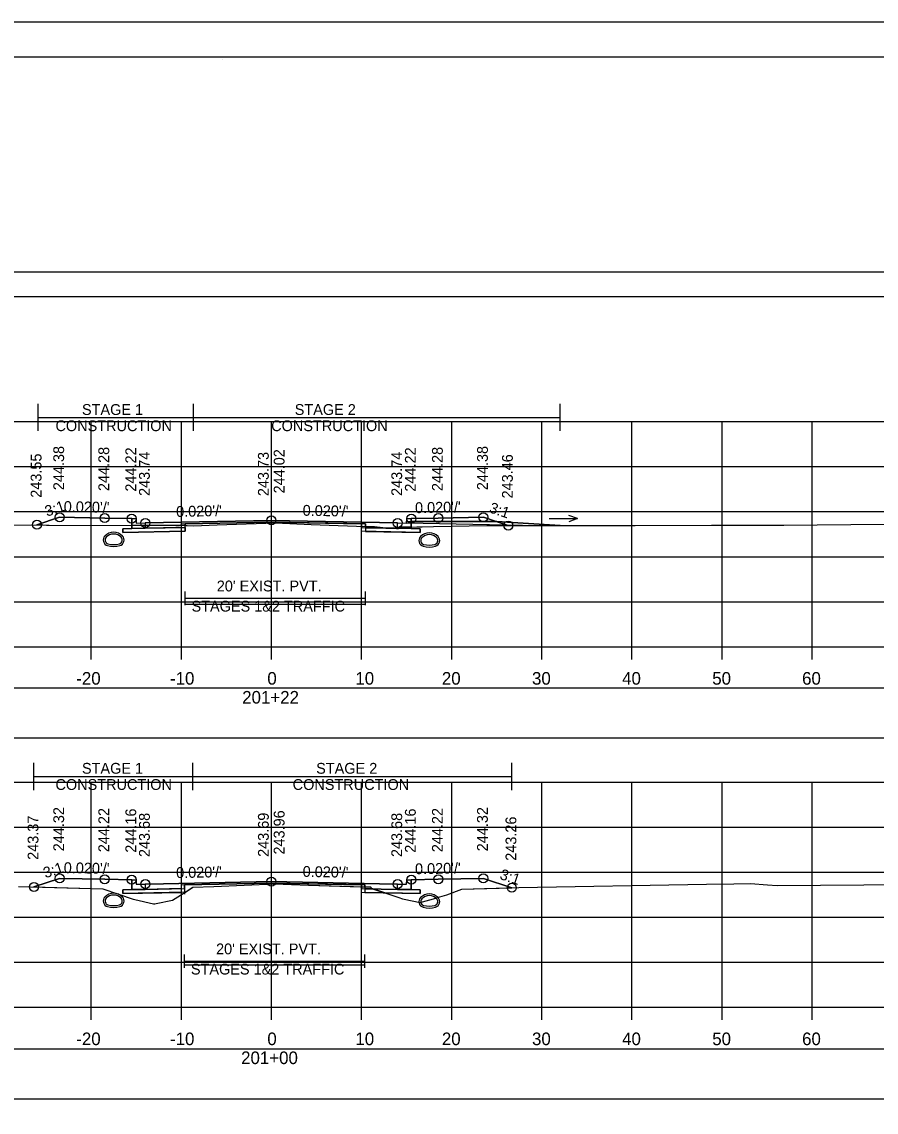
# Model space of a CAD drawing. Extents: x 1369627 to 1374022, y 380035 to 398173.
# Drawn here: x 1372070.8 to 1372165.6, y 380344.5 to 380465.5 of the extents above; entities that cross this region are included whole.
import ezdxf

# ---------------------------------------------------------------- set-up
doc = ezdxf.new("R2010")
doc.units = 0
for name, color, linetype in [('Default', 7, 'Continuous'), ('R_Alt Surface', 7, 'Continuous'), ('R_Axis', 7, 'Continuous'), ('R_Axis Annot', 7, 'Continuous'), ('R_Border', 7, 'Continuous'), ('R_Drive', 7, 'Continuous'), ('R_Exist Surface', 7, 'Continuous'), ('R_Fin Surface', 7, 'Continuous'), ('R_Grid', 7, 'Continuous'), ('R_MOT', 7, 'Continuous'), ('R_No Plot', 7, 'Continuous'), ('R_Water Annot', 7, 'Continuous'), ('R_Xsect Elev', 7, 'Continuous'), ('R_Xsect Slope', 7, 'Continuous'), ('T_Vehicle Path Lt Minor', 7, 'Continuous'), ('T_Vehicle Path Rt', 7, 'Continuous')]:
    doc.layers.add(name, color=color, linetype=linetype)

msp = doc.modelspace()

# ---------------------------------------------------------------- linework, layer by layer
at = {"layer": 'Default'}
for p, q in [((1372088.96, 380400.74), (1372088.96, 380402.24)), ((1372088.96, 380401.49), (1372108.96, 380401.49)), ((1372108.96, 380400.74), (1372108.96, 380402.24)), ((1372088.88, 380360.47), (1372088.88, 380361.97)), ((1372088.88, 380361.22), (1372108.88, 380361.22)), ((1372108.88, 380360.47), (1372108.88, 380361.97))]:
    msp.add_line(p, q, dxfattribs=at)
for points in [[(1371948.53, 380434.98), (1372248.53, 380434.98), (1372248.53, 380437.69), (1371948.53, 380437.69)], [(1372083.02, 380410.32), (1372083.52, 380410.32), (1372083.53, 380409.82), (1372084.53, 380409.84), (1372084.53, 380409.25), (1372083.03, 380409.22)], [(1372113.53, 380409.82), (1372113.54, 380410.32), (1372114.04, 380410.32), (1372114.03, 380409.22), (1372112.53, 380409.25), (1372112.53, 380409.84)], [(1371948.53, 380386.01), (1372248.53, 380386.01), (1372248.53, 380391.53), (1371948.53, 380391.53)], [(1372083.02, 380370.25), (1372083.52, 380370.25), (1372083.53, 380369.75), (1372084.53, 380369.77), (1372084.53, 380369.19), (1372083.03, 380369.16)], [(1372113.53, 380369.75), (1372113.54, 380370.25), (1372114.04, 380370.25), (1372114.03, 380369.16), (1372112.53, 380369.19), (1372112.53, 380369.77)], [(1371948.53, 380345.93), (1372248.53, 380345.93), (1372248.53, 380351.45), (1371948.53, 380351.45)]]:
    msp.add_lwpolyline(points, close=True, dxfattribs=at)
at = {"layer": 'R_Alt Surface'}
for points in [[(1372083.03, 380410.32), (1372083.03, 380409.22), (1372084.53, 380409.25), (1372088.96, 380409.34), (1372088.96, 380409.76), (1372098.53, 380409.95), (1372108.96, 380409.74), (1372108.96, 380409.32), (1372112.53, 380409.25), (1372114.03, 380409.22), (1372114.03, 380410.32)], [(1372083.03, 380370.25), (1372083.03, 380369.16), (1372084.53, 380369.19), (1372088.88, 380369.27), (1372088.88, 380369.69), (1372098.53, 380369.88), (1372108.88, 380369.68), (1372108.88, 380369.26), (1372112.53, 380369.19), (1372114.03, 380369.16), (1372114.03, 380370.25)]]:
    msp.add_lwpolyline(points, dxfattribs=at)
for points in [[(1372082.03, 380409.2), (1372083.03, 380409.22), (1372084.53, 380409.25), (1372088.96, 380409.34), (1372088.96, 380408.92), (1372082.03, 380408.79)], [(1372115.03, 380409.2), (1372114.03, 380409.22), (1372112.53, 380409.25), (1372108.96, 380409.32), (1372108.96, 380408.91), (1372115.03, 380408.79)], [(1372082.03, 380369.14), (1372083.03, 380369.16), (1372084.53, 380369.19), (1372088.88, 380369.27), (1372088.88, 380368.86), (1372082.03, 380368.72)], [(1372115.03, 380369.14), (1372114.03, 380369.16), (1372112.53, 380369.19), (1372108.88, 380369.26), (1372108.88, 380368.84), (1372115.03, 380368.72)]]:
    msp.add_lwpolyline(points, close=True, dxfattribs=at)
at = {"layer": 'R_Axis'}
for p, q in [((1371948.53, 380396.1), (1372248.53, 380396.1)), ((1372078.53, 380394.7), (1372078.53, 380396.1)), ((1372088.53, 380394.7), (1372088.53, 380396.1)), ((1372098.53, 380394.7), (1372098.53, 380396.1)), ((1372108.53, 380394.7), (1372108.53, 380396.1)), ((1372118.53, 380394.7), (1372118.53, 380396.1)), ((1372128.53, 380394.7), (1372128.53, 380396.1)), ((1372138.53, 380394.7), (1372138.53, 380396.1)), ((1372148.53, 380394.7), (1372148.53, 380396.1)), ((1372158.53, 380394.7), (1372158.53, 380396.1)), ((1371948.53, 380356.1), (1372248.53, 380356.1)), ((1372078.53, 380354.7), (1372078.53, 380356.1)), ((1372088.53, 380354.7), (1372088.53, 380356.1)), ((1372098.53, 380354.7), (1372098.53, 380356.1)), ((1372108.53, 380354.7), (1372108.53, 380356.1)), ((1372118.53, 380354.7), (1372118.53, 380356.1)), ((1372128.53, 380354.7), (1372128.53, 380356.1)), ((1372138.53, 380354.7), (1372138.53, 380356.1)), ((1372148.53, 380354.7), (1372148.53, 380356.1)), ((1372158.53, 380354.7), (1372158.53, 380356.1))]:
    msp.add_line(p, q, dxfattribs=at)
at = {"layer": 'R_Border'}
for p, q in [((1371940.53, 380461.56), (1372256.71, 380461.56)), ((1372093.05, 380461.3), (1372093.05, 380461.3)), ((1372093.05, 380461.3), (1372093.05, 380461.3))]:
    msp.add_line(p, q, dxfattribs=at)
at = {"layer": 'R_Drive'}
for p, q in [((1372113.53, 380409.99), (1372123.53, 380410)), ((1372113.53, 380409.82), (1372113.53, 380409.99)), ((1372123.53, 380410), (1372130.57, 380409.58))]:
    msp.add_line(p, q, dxfattribs=at)
for centre, radius, start, end in [((1372080.51, 380407.95), 0.646, 136.3515, 253.9529), ((1372081.02, 380407.46), 1.35, 43.6485, 136.3515), ((1372081.02, 380407.46), 1.15, 43.6485, 136.3515), ((1372081.53, 380407.95), 0.646, 286.0471, 43.6485), ((1372116.04, 380407.4), 1.35, 43.6485, 136.3515), ((1372116.04, 380407.4), 1.15, 43.6485, 136.3515), ((1372080.51, 380407.95), 0.438, 136.3515, 253.9529), ((1372081.02, 380409.73), 2.5, 253.9529, 286.0471), ((1372081.02, 380409.73), 2.29, 253.9529, 286.0471), ((1372081.53, 380407.95), 0.438, 286.0471, 43.6485), ((1372115.53, 380407.89), 0.646, 136.3515, 253.9529), ((1372115.53, 380407.89), 0.438, 136.3515, 253.9529), ((1372116.04, 380409.67), 2.5, 253.9529, 286.0471), ((1372116.04, 380409.67), 2.29, 253.9529, 286.0471), ((1372116.55, 380407.89), 0.438, 286.0471, 43.6485), ((1372116.55, 380407.89), 0.646, 286.0471, 43.6485), ((1372081.02, 380367.4), 1.35, 43.6485, 136.3515), ((1372081.02, 380367.4), 1.15, 43.6485, 136.3515), ((1372116.04, 380367.34), 1.35, 43.6485, 136.3515), ((1372116.04, 380367.34), 1.15, 43.6485, 136.3515), ((1372080.51, 380367.89), 0.646, 136.3515, 253.9529), ((1372080.51, 380367.89), 0.438, 136.3515, 253.9529), ((1372081.02, 380369.67), 2.5, 253.9529, 286.0471), ((1372081.02, 380369.67), 2.29, 253.9529, 286.0471), ((1372081.53, 380367.89), 0.438, 286.0471, 43.6485), ((1372081.53, 380367.89), 0.646, 286.0471, 43.6485), ((1372115.53, 380367.83), 0.646, 136.3515, 253.9529), ((1372115.53, 380367.83), 0.438, 136.3515, 253.9529), ((1372116.04, 380369.61), 2.29, 253.9529, 286.0471), ((1372116.55, 380367.83), 0.438, 286.0471, 43.6485), ((1372116.55, 380367.83), 0.646, 286.0471, 43.6485), ((1372116.04, 380369.61), 2.5, 253.9529, 286.0471)]:
    msp.add_arc(centre, radius, start, end, dxfattribs=at)
at = {"layer": 'R_Exist Surface'}
for points in [[(1372056.85, 380409.49), (1372072.64, 380409.64), (1372073.17, 380409.63), (1372073.56, 380409.61), (1372073.85, 380409.59), (1372087.93, 380409.57), (1372088.19, 380409.57), (1372088.31, 380409.58), (1372088.42, 380409.6), (1372088.45, 380409.6), (1372088.47, 380409.61), (1372089.89, 380409.53), (1372092.52, 380409.62), (1372098.96, 380409.84), (1372102.95, 380409.68), (1372109.96, 380409.42), (1372109.96, 380409.42), (1372111.24, 380409.28), (1372112.39, 380409.24), (1372112.59, 380409.23), (1372112.81, 380409.36), (1372116.51, 380409.45), (1372122.41, 380409.55), (1372130.62, 380409.58), (1372138.89, 380409.58), (1372147.35, 380409.61), (1372155.4, 380409.61), (1372173.95, 380409.77)], [(1372070.47, 380369.51), (1372079.83, 380369.26), (1372083.18, 380368.09), (1372083.35, 380368.05), (1372085.44, 380367.6), (1372085.6, 380367.57), (1372085.74, 380367.62), (1372087.54, 380368), (1372088.72, 380368.71), (1372089.82, 380369.43), (1372092.13, 380369.51), (1372098.88, 380369.8), (1372102.64, 380369.66), (1372109.55, 380369.43), (1372109.63, 380369.29), (1372112.67, 380368.27), (1372113.08, 380368.15), (1372113.25, 380368.1), (1372115.03, 380367.73), (1372116.77, 380368.22), (1372117.22, 380368.37), (1372117.99, 380368.59), (1372119.65, 380369.21), (1372125.96, 380369.38), (1372146.79, 380369.78), (1372149.84, 380369.81), (1372151.7, 380369.84), (1372153.57, 380369.69), (1372154.63, 380369.63), (1372164.28, 380369.7), (1372184.58, 380369.76)]]:
    msp.add_lwpolyline(points, dxfattribs=at)
at = {"layer": 'R_Fin Surface'}
for points in [[(1372072.51, 380409.64), (1372075.02, 380410.48), (1372080.02, 380410.38), (1372083.02, 380410.32), (1372083.52, 380410.32), (1372083.53, 380409.82), (1372084.53, 380409.84), (1372086.53, 380409.88), (1372098.53, 380410.12), (1372110.53, 380409.88), (1372112.53, 380409.84), (1372113.53, 380409.82), (1372113.54, 380410.32), (1372114.04, 380410.32), (1372117.04, 380410.38), (1372122.04, 380410.48), (1372124.81, 380409.56)], [(1372072.17, 380369.46), (1372075.02, 380370.41), (1372080.02, 380370.31), (1372083.02, 380370.25), (1372083.52, 380370.25), (1372083.53, 380369.75), (1372084.53, 380369.77), (1372086.53, 380369.81), (1372098.53, 380370.05), (1372110.53, 380369.81), (1372112.53, 380369.77), (1372113.53, 380369.75), (1372113.54, 380370.25), (1372114.04, 380370.25), (1372117.04, 380370.31), (1372122.04, 380370.41), (1372125.2, 380369.36)]]:
    msp.add_lwpolyline(points, dxfattribs=at)
at = {"layer": 'R_Grid'}
for p, q in [((1371948.53, 380421.1), (1372248.53, 380421.1)), ((1372078.53, 380396.1), (1372078.53, 380421.1)), ((1372088.53, 380396.1), (1372088.53, 380421.1)), ((1372098.53, 380396.1), (1372098.53, 380421.1)), ((1372108.53, 380396.1), (1372108.53, 380421.1)), ((1372118.53, 380396.1), (1372118.53, 380421.1)), ((1372128.53, 380396.1), (1372128.53, 380421.1)), ((1372138.53, 380396.1), (1372138.53, 380421.1)), ((1372148.53, 380396.1), (1372148.53, 380421.1)), ((1372158.53, 380396.1), (1372158.53, 380421.1)), ((1371948.53, 380416.1), (1372248.53, 380416.1)), ((1371948.53, 380411.1), (1372248.53, 380411.1)), ((1371948.53, 380406.1), (1372248.53, 380406.1)), ((1371948.53, 380401.1), (1372248.53, 380401.1)), ((1371948.53, 380396.1), (1372248.53, 380396.1)), ((1371948.53, 380381.1), (1372248.53, 380381.1)), ((1372078.53, 380356.1), (1372078.53, 380381.1)), ((1372088.53, 380356.1), (1372088.53, 380381.1)), ((1372098.53, 380356.1), (1372098.53, 380381.1)), ((1372108.53, 380356.1), (1372108.53, 380381.1)), ((1372118.53, 380356.1), (1372118.53, 380381.1)), ((1372128.53, 380356.1), (1372128.53, 380381.1)), ((1372138.53, 380356.1), (1372138.53, 380381.1)), ((1372148.53, 380356.1), (1372148.53, 380381.1)), ((1372158.53, 380356.1), (1372158.53, 380381.1)), ((1371948.53, 380376.1), (1372248.53, 380376.1)), ((1371948.53, 380371.1), (1372248.53, 380371.1)), ((1371948.53, 380366.1), (1372248.53, 380366.1)), ((1371948.53, 380361.1), (1372248.53, 380361.1)), ((1371948.53, 380356.1), (1372248.53, 380356.1))]:
    msp.add_line(p, q, dxfattribs=at)
at = {"layer": 'R_MOT'}
for p, q in [((1372072.64, 380420.06), (1372072.64, 380423.06)), ((1372089.89, 380420.06), (1372089.89, 380423.06)), ((1372130.57, 380420.06), (1372130.57, 380423.06)), ((1372072.64, 380421.56), (1372130.57, 380421.56)), ((1372072.17, 380380.21), (1372072.17, 380383.21)), ((1372089.82, 380380.21), (1372089.82, 380383.21)), ((1372125.2, 380380.21), (1372125.2, 380383.21)), ((1372072.17, 380381.71), (1372125.2, 380381.71))]:
    msp.add_line(p, q, dxfattribs=at)
at = {"layer": 'R_No Plot'}
for p, q in [((1371928.13, 380465.45), (1372261.46, 380465.45)), ((1372126.4, 380409.56), (1372113.53, 380409.82))]:
    msp.add_line(p, q, dxfattribs=at)
for points in [[(1371928.12, 380465.45), (1372261.46, 380465.45), (1372261.46, 380252.11), (1371928.12, 380252.11)], [(1372174.45, 380461.56), (1372194.07, 380461.56), (1372194.07, 380451.68), (1372210.18, 380451.68), (1372233.38, 380451.68), (1372233.38, 380419.01), (1372256.59, 380419.01), (1372256.71, 380256.1), (1371940.53, 380256.1), (1371940.53, 380461.56)], [(1372098.53, 380410.12), (1372086.53, 380409.88), (1372084.53, 380409.84), (1372084.53, 380409.25), (1372088.53, 380409.33), (1372088.53, 380409.75), (1372098.53, 380409.95), (1372108.53, 380409.75), (1372108.53, 380409.33), (1372112.53, 380409.25), (1372112.53, 380409.84), (1372110.53, 380409.88)], [(1372088.53, 380409.33), (1372084.53, 380409.25), (1372083.03, 380409.22), (1372082.03, 380409.2), (1372082.03, 380408.79), (1372088.53, 380408.92)], [(1372108.53, 380409.33), (1372112.53, 380409.25), (1372114.03, 380409.22), (1372115.03, 380409.2), (1372115.03, 380408.79), (1372108.53, 380408.92)], [(1372098.53, 380370.05), (1372086.53, 380369.81), (1372084.53, 380369.77), (1372084.53, 380369.19), (1372088.53, 380369.27), (1372088.53, 380369.68), (1372098.53, 380369.88), (1372108.53, 380369.68), (1372108.53, 380369.27), (1372112.53, 380369.19), (1372112.53, 380369.77), (1372110.53, 380369.81)], [(1372088.53, 380369.27), (1372084.53, 380369.19), (1372083.03, 380369.16), (1372082.03, 380369.14), (1372082.03, 380368.72), (1372088.53, 380368.85)], [(1372108.53, 380369.27), (1372112.53, 380369.19), (1372114.03, 380369.16), (1372115.03, 380369.14), (1372115.03, 380368.72), (1372108.53, 380368.85)]]:
    msp.add_lwpolyline(points, close=True, dxfattribs=at)
for points in [[(1372083.02, 380410.32), (1372083.03, 380409.22), (1372084.53, 380409.25), (1372088.53, 380409.33), (1372088.53, 380409.75), (1372098.53, 380409.95), (1372108.53, 380409.75), (1372108.53, 380409.33), (1372112.53, 380409.25), (1372114.03, 380409.22), (1372114.04, 380410.32)], [(1372088.96, 380400.84), (1372108.96, 380400.84)], [(1372083.02, 380370.25), (1372083.03, 380369.16), (1372084.53, 380369.19), (1372088.53, 380369.27), (1372088.53, 380369.68), (1372098.53, 380369.88), (1372108.53, 380369.68), (1372108.53, 380369.27), (1372112.53, 380369.19), (1372114.03, 380369.16), (1372114.04, 380370.25)], [(1372088.88, 380360.8), (1372108.88, 380360.8)]]:
    msp.add_lwpolyline(points, dxfattribs=at)
for centre in [(1372075.02, 380410.48), (1372080.02, 380410.38), (1372083.02, 380410.32), (1372114.04, 380410.32), (1372117.04, 380410.38), (1372122.04, 380410.48), (1372072.51, 380409.64), (1372084.53, 380409.84), (1372098.53, 380410.12), (1372112.53, 380409.84), (1372124.81, 380409.56), (1372075.02, 380370.41), (1372122.04, 380370.41), (1372072.17, 380369.46), (1372080.02, 380370.31), (1372083.02, 380370.25), (1372084.53, 380369.77), (1372098.53, 380370.05), (1372112.53, 380369.77), (1372114.04, 380370.25), (1372117.04, 380370.31), (1372125.2, 380369.36)]:
    msp.add_circle(centre, 0.5, dxfattribs=at)
at = {"layer": 'R_Water Annot'}
for p, q in [((1372129.33, 380410.33), (1372132.48, 380410.33)), ((1372132.48, 380410.33), (1372131.52, 380410.68)), ((1372132.48, 380410.33), (1372131.52, 380409.98))]:
    msp.add_line(p, q, dxfattribs=at)
at = {"layer": 'R_Xsect Elev'}
for p, q in [((1372098.53, 380409.82), (1372098.53, 380419.82)), ((1372098.53, 380369.79), (1372098.53, 380379.79))]:
    msp.add_line(p, q, dxfattribs=at)
at = {"layer": 'T_Vehicle Path Lt Minor'}
for p, q in [((1372123.53, 380410), (1372123.48, 380410)), ((1372130.57, 380409.58), (1372123.53, 380410)), ((1372124.81, 380409.56), (1372130.57, 380409.58))]:
    msp.add_line(p, q, dxfattribs=at)
msp.add_lwpolyline([(1372123.48, 380410), (1372124.69, 380409.6), (1372124.81, 380409.56)], dxfattribs=at)
at = {"layer": 'T_Vehicle Path Rt'}
for p, q in [((1372083.03, 380409.58), (1372083.02, 380410.32)), ((1372084.53, 380409.58), (1372083.03, 380409.58)), ((1372083.03, 380409.58), (1372083.03, 380409.22)), ((1372084.53, 380409.58), (1372084.53, 380409.25)), ((1372108.96, 380409.45), (1372108.96, 380409.74)), ((1372114.04, 380409.99), (1372114.03, 380409.39)), ((1372114.04, 380410.32), (1372114.04, 380409.99)), ((1372123.48, 380410), (1372114.04, 380409.99)), ((1372114.04, 380409.99), (1372123.48, 380410)), ((1372124.81, 380409.56), (1372123.48, 380410)), ((1372088.96, 380409.34), (1372084.53, 380409.25)), ((1372108.96, 380409.45), (1372108.96, 380409.32)), ((1372111.23, 380409.28), (1372108.96, 380409.32)), ((1372108.96, 380409.32), (1372111.23, 380409.28)), ((1372114.03, 380409.22), (1372112.62, 380409.25)), ((1372112.62, 380409.25), (1372114.03, 380409.22)), ((1372114.03, 380409.22), (1372114.03, 380409.39)), ((1372083.03, 380369.16), (1372083.02, 380370.25)), ((1372108.88, 380369.45), (1372108.88, 380369.68)), ((1372114.04, 380370.25), (1372114.03, 380369.16)), ((1372088.88, 380369.27), (1372088.88, 380368.86)), ((1372088.88, 380368.86), (1372088.88, 380368.64)), ((1372088.88, 380368.81), (1372088.88, 380368.86)), ((1372088.88, 380368.86), (1372088.88, 380368.81)), ((1372108.88, 380369.45), (1372108.88, 380369.26)), ((1372109.78, 380369.24), (1372108.88, 380369.26)), ((1372108.88, 380369.26), (1372109.78, 380369.24)), ((1372111.11, 380368.8), (1372109.78, 380369.24)), ((1372111.11, 380368.8), (1372112.67, 380368.27))]:
    msp.add_line(p, q, dxfattribs=at)
for points in [[(1372083.02, 380410.32), (1372080.02, 380410.38), (1372075.02, 380410.48), (1372072.51, 380409.64)], [(1372072.51, 380409.64), (1372072.64, 380409.64), (1372073.17, 380409.63), (1372073.56, 380409.61), (1372073.85, 380409.59), (1372083.03, 380409.58)], [(1372083.03, 380409.22), (1372084.53, 380409.25), (1372084.53, 380409.58)], [(1372088.96, 380409.58), (1372088.47, 380409.61), (1372088.45, 380409.6), (1372088.42, 380409.6), (1372088.31, 380409.58), (1372088.19, 380409.57), (1372087.93, 380409.57), (1372084.53, 380409.58)], [(1372084.53, 380409.25), (1372088.96, 380409.34), (1372088.96, 380409.58)], [(1372108.96, 380409.74), (1372098.53, 380409.95), (1372088.96, 380409.76), (1372088.96, 380409.58)], [(1372088.96, 380409.58), (1372089.89, 380409.53), (1372092.52, 380409.62), (1372098.96, 380409.84), (1372102.95, 380409.68), (1372108.96, 380409.45)], [(1372123.48, 380410), (1372122.04, 380410.48), (1372117.04, 380410.38), (1372114.04, 380410.32)], [(1372084.53, 380409.25), (1372083.03, 380409.22), (1372082.03, 380409.2), (1372082.03, 380408.79), (1372088.96, 380408.92), (1372088.96, 380409.34)], [(1372111.23, 380409.28), (1372109.96, 380409.42), (1372108.96, 380409.45)], [(1372108.96, 380409.32), (1372108.96, 380408.91), (1372115.03, 380408.79), (1372115.03, 380409.2), (1372114.03, 380409.22)], [(1372112.62, 380409.25), (1372112.59, 380409.23), (1372112.39, 380409.24), (1372111.24, 380409.28), (1372111.23, 380409.28)], [(1372114.03, 380409.39), (1372112.81, 380409.36), (1372112.62, 380409.25)], [(1372114.03, 380409.39), (1372116.51, 380409.45), (1372122.41, 380409.55), (1372124.81, 380409.56)], [(1372083.02, 380370.25), (1372080.02, 380370.31), (1372075.02, 380370.41), (1372072.17, 380369.46)], [(1372108.88, 380369.68), (1372098.53, 380369.88), (1372088.88, 380369.69), (1372088.88, 380369.27)], [(1372088.88, 380368.81), (1372089.82, 380369.43), (1372092.13, 380369.51), (1372098.88, 380369.8), (1372102.64, 380369.66), (1372108.88, 380369.45)], [(1372125.2, 380369.36), (1372122.04, 380370.41), (1372117.04, 380370.31), (1372114.04, 380370.25)], [(1372072.17, 380369.46), (1372079.83, 380369.26), (1372083.18, 380368.09), (1372083.35, 380368.05), (1372085.44, 380367.6), (1372085.6, 380367.57), (1372085.74, 380367.62), (1372087.54, 380368), (1372088.72, 380368.71), (1372088.88, 380368.81)], [(1372088.88, 380368.86), (1372082.03, 380368.72), (1372082.03, 380369.14), (1372083.03, 380369.16)], [(1372109.78, 380369.24), (1372109.63, 380369.29), (1372109.55, 380369.43), (1372108.88, 380369.45)], [(1372108.88, 380369.26), (1372108.88, 380368.84), (1372111.11, 380368.8)], [(1372114.03, 380369.16), (1372115.03, 380369.14), (1372115.03, 380368.72), (1372111.11, 380368.8)], [(1372112.67, 380368.27), (1372113.08, 380368.15), (1372113.25, 380368.1), (1372115.03, 380367.73), (1372116.77, 380368.22), (1372117.22, 380368.37), (1372117.99, 380368.59), (1372119.65, 380369.21), (1372125.2, 380369.36)]]:
    msp.add_lwpolyline(points, dxfattribs=at)

# ---------------------------------------------------------------- texts
at = {"layer": 'R_Axis Annot'}
for s, height, p in [("20' EXIST. PVT.", 1.2, (1372092.46, 380402.25)), ('STAGES 1&2 TRAFFIC', 1.2, (1372089.66, 380400.01)), ('-20', 1.4, (1372076.87, 380391.9)), ('-10', 1.4, (1372087.27, 380391.9)), ('0', 1.4, (1372098.07, 380391.9)), ('10', 1.4, (1372107.84, 380391.9)), ('20', 1.4, (1372117.44, 380391.9)), ('30', 1.4, (1372127.44, 380391.9)), ('40', 1.4, (1372137.44, 380391.9)), ('50', 1.4, (1372147.44, 380391.9)), ('60', 1.4, (1372157.41, 380391.9)), ('201+22', 1.4, (1372095.28, 380389.8)), ("20' EXIST. PVT.", 1.2, (1372092.38, 380361.98)), ('STAGES 1&2 TRAFFIC', 1.2, (1372089.59, 380359.74)), ('-20', 1.4, (1372076.87, 380351.9)), ('-10', 1.4, (1372087.27, 380351.9)), ('0', 1.4, (1372098.07, 380351.9)), ('10', 1.4, (1372107.84, 380351.9)), ('20', 1.4, (1372117.44, 380351.9)), ('30', 1.4, (1372127.44, 380351.9)), ('40', 1.4, (1372137.44, 380351.9)), ('50', 1.4, (1372147.44, 380351.9)), ('60', 1.4, (1372157.41, 380351.9)), ('201+00', 1.4, (1372095.16, 380349.8))]:
    msp.add_text(s, height=height, dxfattribs=at).set_placement(p)
at = {"layer": 'R_MOT'}
for s, p in [('STAGE 1', (1372077.5, 380421.83)), ('STAGE 2', (1372101.11, 380421.83)), ('CONSTRUCTION', (1372074.56, 380420.03)), ('CONSTRUCTION', (1372098.5, 380420.03)), ('STAGE 1', (1372077.5, 380382.02)), ('STAGE 2', (1372103.49, 380382.02)), ('CONSTRUCTION', (1372074.56, 380380.22)), ('CONSTRUCTION', (1372100.88, 380380.22))]:
    msp.add_text(s, height=1.2, dxfattribs=at).set_placement(p)
at = {"layer": 'R_Xsect Elev'}
for s, p in [('244.38', (1372075.52, 380413.48)), ('244.28', (1372080.52, 380413.38)), ('244.22', (1372083.52, 380413.32)), ('244.22', (1372114.54, 380413.32)), ('244.28', (1372117.54, 380413.38)), ('244.38', (1372122.54, 380413.48)), ('243.55', (1372073.01, 380412.64)), ('243.74', (1372085.03, 380412.84)), ('243.73', (1372098.23, 380412.82)), ('244.02', (1372099.98, 380413.12)), ('243.74', (1372113.03, 380412.84)), ('243.46', (1372125.31, 380412.56)), ('244.32', (1372075.52, 380373.41)), ('244.22', (1372080.52, 380373.31)), ('244.22', (1372117.54, 380373.31)), ('244.32', (1372122.54, 380373.41)), ('243.37', (1372072.67, 380372.46)), ('244.16', (1372083.52, 380373.25)), ('243.68', (1372085.03, 380372.77)), ('243.69', (1372098.23, 380372.79)), ('243.96', (1372099.98, 380373.05)), ('243.68', (1372113.03, 380372.77)), ('244.16', (1372114.54, 380373.25)), ('243.26', (1372125.7, 380372.36))]:
    msp.add_text(s, height=1.2, rotation=90, dxfattribs=at).set_placement(p)
at = {"layer": 'R_Xsect Slope'}
for s, rotation, p in [('3:1', 18.4332, (1372073.61, 380410.53)), ("0.020'/'", 358.8542, (1372075.47, 380411.07)), ("0.020'/'", 1.1458, (1372114.47, 380410.93)), ('3:1', 341.5668, (1372122.61, 380411.04)), ("0.020'/'", 1.1458, (1372087.96, 380410.51)), ("0.020'/'", 358.8542, (1372101.98, 380410.65)), ('3:1', 18.4332, (1372073.44, 380370.41)), ("0.020'/'", 358.8542, (1372075.47, 380371)), ("0.020'/'", 1.1458, (1372114.47, 380370.86)), ("0.020'/'", 1.1458, (1372087.96, 380370.44)), ("0.020'/'", 358.8542, (1372101.98, 380370.58)), ('3:1', 341.5668, (1372123.78, 380370.36))]:
    msp.add_text(s, height=1.2, rotation=rotation, dxfattribs=at).set_placement(p)

doc.saveas('drawing.dxf')
